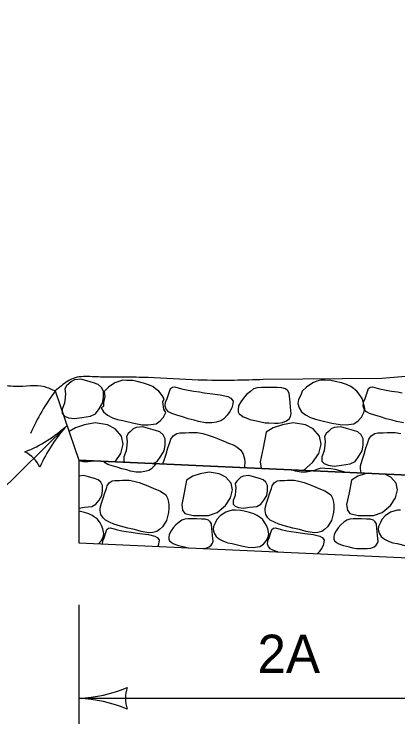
# Model space of a CAD drawing. Extents: x 49991.4 to 50021, y 49987.6 to 50011.4.
# Drawn here: x 50001.389 to 50001.992, y 49990.791 to 49991.906 of the extents above; entities that cross this region are included whole.
import ezdxf

# ---------------------------------------------------------------- set-up
doc = ezdxf.new("R2010")
doc.units = 0
for name, color, linetype in [('Level 1', 7, 'Continuous'), ('Level 2', 7, 'Continuous'), ('Level 3', 7, 'Continuous')]:
    doc.layers.add(name, color=color, linetype=linetype)

msp = doc.modelspace()

# ---------------------------------------------------------------- linework, layer by layer
at = {"layer": 'Level 1'}
for p, q in [((50001.4535, 49991.3139), (50001.4905, 49991.2052)), ((50001.4905, 49991.2052), (50001.4905, 49991.0752))]:
    msp.add_line(p, q, dxfattribs=at)
for points in [[(50006.8341, 49992.9155), (50006.2939, 49992.7804), (50006.1193, 49992.7186), (50006.0287, 49992.663), (50005.1465, 49992.663), (50002.1692, 49991.1744), (50001.4905, 49991.2052)], [(50002.2619, 49991.3557), (50002.1973, 49991.353), (50001.9665, 49991.3333), (50001.7803, 49991.3318)], [(50002.0003, 49991.2638), (50001.9897, 49991.2658), (50001.9826, 49991.268), (50001.9734, 49991.2703), (50001.9643, 49991.2734), (50001.9552, 49991.2757), (50001.9473, 49991.2783), (50001.9422, 49991.2813), (50001.9387, 49991.2855), (50001.937, 49991.29), (50001.9375, 49991.2963), (50001.9402, 49991.3021), (50001.9427, 49991.3099), (50001.9454, 49991.3175), (50001.9483, 49991.32), (50001.952, 49991.3204), (50001.9626, 49991.3173), (50001.9734, 49991.3151), (50001.9818, 49991.3137), (50001.9912, 49991.3124), (50001.9986, 49991.311)], [(50001.5475, 49991.2026), (50001.5565, 49991.2157), (50001.5604, 49991.2304), (50001.5575, 49991.243), (50001.5476, 49991.2546), (50001.5353, 49991.2609), (50001.5161, 49991.2636), (50001.4994, 49991.2609), (50001.4851, 49991.256), (50001.4752, 49991.25)], [(50001.607, 49991.1999), (50001.6137, 49991.2033), (50001.6194, 49991.2112), (50001.6246, 49991.2199), (50001.6263, 49991.2286), (50001.626, 49991.2385), (50001.6228, 49991.2448), (50001.6179, 49991.2495), (50001.6108, 49991.2519), (50001.5999, 49991.2551), (50001.5908, 49991.2575), (50001.5805, 49991.2564), (50001.5758, 49991.2542), (50001.5716, 49991.2501), (50001.5682, 49991.247), (50001.5655, 49991.2423), (50001.5665, 49991.2345), (50001.566, 49991.2289), (50001.565, 49991.2197), (50001.561, 49991.2105), (50001.5613, 49991.2036), (50001.5629, 49991.2019)], [(50001.8438, 49991.1892), (50001.8576, 49991.2013), (50001.8674, 49991.2157), (50001.8714, 49991.2304), (50001.8684, 49991.243), (50001.8586, 49991.2546), (50001.8463, 49991.2609), (50001.8271, 49991.2636), (50001.8103, 49991.2609), (50001.796, 49991.256), (50001.7846, 49991.249), (50001.7798, 49991.2246), (50001.7754, 49991.2027), (50001.7768, 49991.1924), (50001.7769, 49991.1922)], [(50001.6227, 49991.1992), (50001.6243, 49991.2052), (50001.6275, 49991.2148), (50001.6305, 49991.2246), (50001.6334, 49991.2329), (50001.6349, 49991.2383), (50001.6388, 49991.2435), (50001.6442, 49991.2473), (50001.6494, 49991.2479), (50001.6578, 49991.2482), (50001.6637, 49991.2488), (50001.6763, 49991.2486), (50001.6854, 49991.2468), (50001.6952, 49991.2441), (50001.7031, 49991.2414), (50001.7085, 49991.2392), (50001.7174, 49991.2356), (50001.7257, 49991.232), (50001.7344, 49991.2289), (50001.7393, 49991.2255), (50001.7452, 49991.2208), (50001.7486, 49991.2146), (50001.7506, 49991.2072), (50001.7511, 49991.2023), (50001.7509, 49991.1951), (50001.7507, 49991.1934)], [(50001.9338, 49991.1851), (50001.9328, 49991.1913), (50001.9328, 49991.196), (50001.9353, 49991.2052), (50001.9385, 49991.2148), (50001.9414, 49991.2246), (50001.9444, 49991.2329), (50001.9458, 49991.2383), (50001.9498, 49991.2435), (50001.9552, 49991.2473), (50001.9604, 49991.2479), (50001.9687, 49991.2482), (50001.9747, 49991.2488), (50001.9872, 49991.2486), (50001.9963, 49991.2468)], [(50001.4905, 49991.2052), (50002.1692, 49991.1744)], [(50001.4905, 49991.2046), (50001.4975, 49991.2033), (50001.5053, 49991.2031), (50001.5138, 49991.2041)], [(50001.6114, 49991.1997), (50001.6087, 49991.1962), (50001.6046, 49991.1917), (50001.6005, 49991.1891), (50001.5944, 49991.1872), (50001.5886, 49991.1861), (50001.5804, 49991.1863), (50001.5716, 49991.188), (50001.5657, 49991.1898), (50001.5581, 49991.1917), (50001.5505, 49991.1943), (50001.5429, 49991.1962), (50001.5363, 49991.1984), (50001.532, 49991.2008), (50001.5299, 49991.2034)], [(50001.9082, 49991.1862), (50001.903, 49991.1879), (50001.8929, 49991.1904), (50001.8863, 49991.1917), (50001.8767, 49991.192), (50001.8708, 49991.1924), (50001.8641, 49991.1906), (50001.859, 49991.1885)], [(50001.4905, 49991.1298), (50001.4994, 49991.1311), (50001.5109, 49991.1326), (50001.5174, 49991.1359), (50001.5222, 49991.1424), (50001.5265, 49991.1497), (50001.5279, 49991.157), (50001.5277, 49991.1652), (50001.525, 49991.1704), (50001.5209, 49991.1743), (50001.515, 49991.1764), (50001.5059, 49991.179), (50001.4984, 49991.1811), (50001.4905, 49991.1802)], [(50001.8578, 49991.1885), (50001.8535, 49991.1872), (50001.8478, 49991.1861), (50001.8396, 49991.1863), (50001.8307, 49991.188), (50001.8248, 49991.1898), (50001.8238, 49991.1901)], [(50001.919, 49991.174), (50001.9149, 49991.1536), (50001.9112, 49991.1354), (50001.9125, 49991.1268), (50001.9162, 49991.1212), (50001.9293, 49991.1182), (50001.9535, 49991.1182), (50001.9671, 49991.123), (50001.9798, 49991.1342), (50001.988, 49991.1462), (50001.9913, 49991.1585), (50001.9888, 49991.1689), (50001.9806, 49991.1786), (50001.9713, 49991.1834)], [(50001.9448, 49991.1846), (50001.9404, 49991.1839), (50001.9285, 49991.1798), (50001.919, 49991.174)], [(50001.5216, 49991.0738), (50001.5254, 49991.0783), (50001.5287, 49991.0843), (50001.5298, 49991.0895), (50001.5283, 49991.0971), (50001.5263, 49991.1026), (50001.5238, 49991.1067), (50001.5197, 49991.1123), (50001.5152, 49991.1156), (50001.5117, 49991.1184), (50001.5062, 49991.1208), (50001.4994, 49991.1231), (50001.491, 49991.1251), (50001.4905, 49991.1252)], [(50001.9957, 49991.1264), (50001.9908, 49991.1268), (50001.9852, 49991.1253), (50001.9803, 49991.1233)], [(50001.6857, 49991.0663), (50001.69, 49991.0669), (50001.6953, 49991.0692), (50001.6986, 49991.0718), (50001.7004, 49991.0747), (50001.7015, 49991.0781), (50001.7007, 49991.0869), (50001.7, 49991.093), (50001.6996, 49991.0975), (50001.6988, 49991.1052), (50001.697, 49991.1083), (50001.6941, 49991.1111), (50001.6892, 49991.1124), (50001.6832, 49991.1126), (50001.6756, 49991.1128), (50001.668, 49991.1128), (50001.6623, 49991.1128), (50001.6569, 49991.1123)], [(50001.9803, 49991.1233), (50001.9717, 49991.1175), (50001.9663, 49991.1121), (50001.9643, 49991.107), (50001.9614, 49991.1012), (50001.9606, 49991.096), (50001.9622, 49991.0904), (50001.9655, 49991.0854), (50001.9707, 49991.0811), (50001.977, 49991.0777), (50001.9838, 49991.0755), (50001.9906, 49991.074), (50002.0049, 49991.0705)], [(50001.6569, 49991.1123), (50001.6522, 49991.1108), (50001.6479, 49991.1076), (50001.643, 49991.1035), (50001.6389, 49991.0988), (50001.6356, 49991.0942), (50001.6325, 49991.0886), (50001.6319, 49991.0841), (50001.6319, 49991.0809), (50001.6331, 49991.0785), (50001.6358, 49991.0764), (50001.6387, 49991.0744), (50001.6426, 49991.0729), (50001.6471, 49991.071), (50001.6516, 49991.0699), (50001.6561, 49991.0692), (50001.6615, 49991.0677), (50001.663, 49991.0674)], [(50001.5277, 49991.0735), (50001.5281, 49991.0785), (50001.5304, 49991.0833), (50001.5324, 49991.0899), (50001.5347, 49991.0962)], [(50001.5347, 49991.0962), (50001.5371, 49991.0983), (50001.5402, 49991.0986), (50001.549, 49991.096), (50001.5581, 49991.0942), (50001.565, 49991.093), (50001.5728, 49991.0919), (50001.579, 49991.0908), (50001.5864, 49991.09), (50001.5997, 49991.0882), (50001.61, 49991.0859), (50001.6137, 49991.0837), (50001.6165, 49991.08), (50001.6161, 49991.0762), (50001.6151, 49991.0712), (50001.6142, 49991.0696)], [(50001.8033, 49991.061), (50001.802, 49991.0613), (50001.7954, 49991.0636), (50001.7911, 49991.066), (50001.7883, 49991.0695), (50001.7868, 49991.0733), (50001.7872, 49991.0785), (50001.7895, 49991.0833), (50001.7915, 49991.0899), (50001.7938, 49991.0962)], [(50001.7938, 49991.0962), (50001.7963, 49991.0983), (50001.7993, 49991.0986), (50001.8082, 49991.096), (50001.8172, 49991.0942), (50001.8242, 49991.093), (50001.832, 49991.0919), (50001.8381, 49991.0908), (50001.8455, 49991.09), (50001.8588, 49991.0882), (50001.8691, 49991.0859), (50001.8728, 49991.0837), (50001.8757, 49991.08), (50001.8753, 49991.0762), (50001.8742, 49991.0712), (50001.8716, 49991.0662), (50001.8679, 49991.0613), (50001.865, 49991.0582)], [(50001.4905, 49991.0752), (50002.1692, 49991.0444)]]:
    msp.add_lwpolyline(points, dxfattribs=at)
for points in [[(50001.4905, 49991.2052), (50001.4905, 49991.0752), (50002.1692, 49991.0444), (50005.1465, 49992.533), (50006.0287, 49992.533), (50006.0287, 49992.663), (50005.1465, 49992.663), (50002.1692, 49991.1744)], [(50001.4835, 49991.3312), (50001.4788, 49991.3289), (50001.4746, 49991.3249), (50001.4712, 49991.3218), (50001.4685, 49991.3171), (50001.4695, 49991.3092), (50001.469, 49991.3036), (50001.468, 49991.2945), (50001.4641, 49991.2853), (50001.4643, 49991.2783), (50001.468, 49991.2745), (50001.4744, 49991.2718), (50001.4838, 49991.2707), (50001.4951, 49991.2723), (50001.5089, 49991.2741), (50001.5167, 49991.2781), (50001.5224, 49991.2859), (50001.5276, 49991.2947), (50001.5293, 49991.3034), (50001.5291, 49991.3133), (50001.5259, 49991.3195), (50001.5209, 49991.3242), (50001.5138, 49991.3267), (50001.503, 49991.3298), (50001.4939, 49991.3323)], [(50001.5473, 49991.3266), (50001.5369, 49991.3196), (50001.5305, 49991.3131), (50001.5315, 49991.3054), (50001.5293, 49991.2959), (50001.5291, 49991.2895), (50001.5256, 49991.2872), (50001.5295, 49991.2811), (50001.5357, 49991.276), (50001.5433, 49991.2719), (50001.5514, 49991.2692), (50001.5596, 49991.2675), (50001.5768, 49991.2632), (50001.5899, 49991.2607), (50001.5992, 49991.2605), (50001.6118, 49991.2621), (50001.6184, 49991.2668), (50001.6233, 49991.2726), (50001.6273, 49991.2798), (50001.6241, 49991.2852), (50001.6223, 49991.2966), (50001.6243, 49991.3017), (50001.6214, 49991.3066), (50001.6164, 49991.3134), (50001.611, 49991.3174), (50001.6068, 49991.3207), (50001.6002, 49991.3237), (50001.5921, 49991.3263), (50001.582, 49991.3288), (50001.5753, 49991.3302), (50001.5657, 49991.3304), (50001.5598, 49991.3308), (50001.5532, 49991.329)], [(50001.8582, 49991.3268), (50001.8479, 49991.3198), (50001.8415, 49991.3133), (50001.839, 49991.3073), (50001.8356, 49991.3004), (50001.8346, 49991.2941), (50001.8365, 49991.2874), (50001.8405, 49991.2813), (50001.8466, 49991.2762), (50001.8543, 49991.2721), (50001.8624, 49991.2695), (50001.8705, 49991.2677), (50001.8878, 49991.2634), (50001.9008, 49991.261), (50001.9102, 49991.2607), (50001.9227, 49991.2623), (50001.9294, 49991.267), (50001.9343, 49991.2728), (50001.9382, 49991.28), (50001.9395, 49991.2863), (50001.9377, 49991.2954), (50001.9353, 49991.3019), (50001.9323, 49991.3069), (50001.9274, 49991.3136), (50001.922, 49991.3176), (50001.9178, 49991.321), (50001.9111, 49991.3239), (50001.903, 49991.3266), (50001.8929, 49991.329), (50001.8863, 49991.3304), (50001.8767, 49991.3306), (50001.8708, 49991.331), (50001.8641, 49991.3292)], [(50001.6344, 49991.3175), (50001.6374, 49991.32), (50001.6411, 49991.3204), (50001.6517, 49991.3173), (50001.6625, 49991.3151), (50001.6709, 49991.3137), (50001.6802, 49991.3124), (50001.6876, 49991.311), (50001.6965, 49991.3101), (50001.7125, 49991.3079), (50001.7248, 49991.3052), (50001.7292, 49991.3025), (50001.7327, 49991.2981), (50001.7322, 49991.2936), (50001.7309, 49991.2875), (50001.7277, 49991.2815), (50001.7233, 49991.2757), (50001.7184, 49991.2703), (50001.7135, 49991.2672), (50001.7061, 49991.2649), (50001.6992, 49991.2636), (50001.6893, 49991.2638), (50001.6787, 49991.2658), (50001.6716, 49991.268), (50001.6625, 49991.2703), (50001.6534, 49991.2734), (50001.6443, 49991.2757), (50001.6364, 49991.2783), (50001.6312, 49991.2813), (50001.6278, 49991.2855), (50001.626, 49991.29), (50001.6265, 49991.2963), (50001.6292, 49991.3021), (50001.6317, 49991.3099)], [(50001.7708, 49991.3187), (50001.7651, 49991.317), (50001.7599, 49991.3131), (50001.754, 49991.3082), (50001.7491, 49991.3026), (50001.7452, 49991.297), (50001.7415, 49991.2903), (50001.7407, 49991.2849), (50001.7407, 49991.2811), (50001.7422, 49991.2782), (50001.7454, 49991.2758), (50001.7488, 49991.2733), (50001.7535, 49991.2715), (50001.7589, 49991.2693), (50001.7644, 49991.2679), (50001.7698, 49991.267), (50001.7762, 49991.2652), (50001.7833, 49991.2639), (50001.7892, 49991.2639), (50001.7976, 49991.2634), (50001.8038, 49991.2634), (50001.8104, 49991.2643), (50001.8168, 49991.267), (50001.8207, 49991.2702), (50001.823, 49991.2737), (50001.8242, 49991.2778), (50001.8232, 49991.2883), (50001.8225, 49991.2957), (50001.822, 49991.3011), (50001.821, 49991.3102), (50001.8188, 49991.314), (50001.8153, 49991.3174), (50001.8094, 49991.319), (50001.8023, 49991.3192), (50001.7932, 49991.3194), (50001.7841, 49991.3194), (50001.7772, 49991.3194)], [(50001.8914, 49991.2564), (50001.8868, 49991.2542), (50001.8826, 49991.2501), (50001.8791, 49991.247), (50001.8764, 49991.2423), (50001.8774, 49991.2345), (50001.8769, 49991.2289), (50001.8759, 49991.2197), (50001.872, 49991.2105), (50001.8722, 49991.2036), (50001.8759, 49991.1998), (50001.8823, 49991.1971), (50001.8917, 49991.1959), (50001.903, 49991.1975), (50001.9168, 49991.1993), (50001.9247, 49991.2033), (50001.9303, 49991.2112), (50001.9355, 49991.2199), (50001.9372, 49991.2286), (50001.937, 49991.2385), (50001.9338, 49991.2448), (50001.9289, 49991.2495), (50001.9217, 49991.2519), (50001.9109, 49991.2551), (50001.9018, 49991.2575)], [(50001.6598, 49991.174), (50001.6558, 49991.1536), (50001.6521, 49991.1354), (50001.6534, 49991.1268), (50001.657, 49991.1212), (50001.6702, 49991.1182), (50001.6944, 49991.1182), (50001.7079, 49991.123), (50001.7207, 49991.1342), (50001.7289, 49991.1462), (50001.7321, 49991.1585), (50001.7297, 49991.1689), (50001.7215, 49991.1786), (50001.7112, 49991.1839), (50001.6952, 49991.1861), (50001.6813, 49991.1839), (50001.6694, 49991.1798)], [(50001.7489, 49991.1801), (50001.745, 49991.1783), (50001.7415, 49991.1749), (50001.7386, 49991.1723), (50001.7363, 49991.1684), (50001.7372, 49991.1618), (50001.7368, 49991.1572), (50001.7359, 49991.1495), (50001.7327, 49991.1419), (50001.7329, 49991.1361), (50001.7359, 49991.1329), (50001.7413, 49991.1307), (50001.7491, 49991.1298), (50001.7585, 49991.1311), (50001.77, 49991.1326), (50001.7766, 49991.1359), (50001.7813, 49991.1424), (50001.7856, 49991.1497), (50001.787, 49991.157), (50001.7868, 49991.1652), (50001.7842, 49991.1704), (50001.7801, 49991.1743), (50001.7741, 49991.1764), (50001.7651, 49991.179), (50001.7575, 49991.1811)], [(50001.5472, 49991.1731), (50001.5542, 49991.1733), (50001.5591, 49991.1738), (50001.5695, 49991.1736), (50001.5771, 49991.1721), (50001.5853, 49991.1699), (50001.5919, 49991.1677), (50001.5964, 49991.1658), (50001.6038, 49991.1628), (50001.6108, 49991.1598), (50001.618, 49991.1572), (50001.6221, 49991.1544), (50001.627, 49991.1505), (50001.6299, 49991.1453), (50001.6315, 49991.1391), (50001.6319, 49991.135), (50001.6317, 49991.129), (50001.6313, 49991.1231), (50001.6297, 49991.1165), (50001.6282, 49991.1102), (50001.6258, 49991.1061), (50001.6219, 49991.1005), (50001.6171, 49991.0962), (50001.6128, 49991.0932), (50001.6067, 49991.0914), (50001.6007, 49991.0908), (50001.5886, 49991.0932), (50001.5782, 49991.096), (50001.5677, 49991.0981), (50001.5562, 49991.1016), (50001.5457, 49991.1048), (50001.5388, 49991.1076), (50001.5322, 49991.1111), (50001.5285, 49991.1147), (50001.5252, 49991.1197), (50001.5242, 49991.1259), (50001.5242, 49991.1298), (50001.5262, 49991.1374), (50001.5289, 49991.1455), (50001.5314, 49991.1537), (50001.5338, 49991.1606), (50001.5351, 49991.1651), (50001.5384, 49991.1693), (50001.5429, 49991.1725)], [(50001.8063, 49991.1731), (50001.8133, 49991.1733), (50001.8182, 49991.1738), (50001.8287, 49991.1736), (50001.8363, 49991.1721), (50001.8445, 49991.1699), (50001.851, 49991.1677), (50001.8555, 49991.1658), (50001.8629, 49991.1628), (50001.8699, 49991.1598), (50001.8771, 49991.1572), (50001.8812, 49991.1544), (50001.8861, 49991.1505), (50001.889, 49991.1453), (50001.8906, 49991.1391), (50001.891, 49991.135), (50001.8908, 49991.129), (50001.8904, 49991.1231), (50001.8888, 49991.1165), (50001.8873, 49991.1102), (50001.8849, 49991.1061), (50001.881, 49991.1005), (50001.8763, 49991.0962), (50001.872, 49991.0932), (50001.8658, 49991.0914), (50001.8599, 49991.0908), (50001.8477, 49991.0932), (50001.8373, 49991.096), (50001.8268, 49991.0981), (50001.8153, 49991.1016), (50001.8049, 49991.1048), (50001.7979, 49991.1076), (50001.7913, 49991.1111), (50001.7876, 49991.1147), (50001.7843, 49991.1197), (50001.7833, 49991.1259), (50001.7833, 49991.1298), (50001.7854, 49991.1374), (50001.788, 49991.1455), (50001.7905, 49991.1537), (50001.793, 49991.1606), (50001.7942, 49991.1651), (50001.7975, 49991.1693), (50001.802, 49991.1725)], [(50001.7212, 49991.1233), (50001.7126, 49991.1175), (50001.7072, 49991.1121), (50001.7052, 49991.107), (50001.7023, 49991.1012), (50001.7015, 49991.096), (50001.7031, 49991.0904), (50001.7064, 49991.0854), (50001.7115, 49991.0811), (50001.7179, 49991.0777), (50001.7247, 49991.0755), (50001.7314, 49991.074), (50001.7458, 49991.0705), (50001.7567, 49991.0684), (50001.7645, 49991.0682), (50001.7749, 49991.0695), (50001.7805, 49991.0734), (50001.7846, 49991.0783), (50001.7879, 49991.0843), (50001.7889, 49991.0895), (50001.7874, 49991.0971), (50001.7854, 49991.1026), (50001.7829, 49991.1067), (50001.7788, 49991.1123), (50001.7743, 49991.1156), (50001.7708, 49991.1184), (50001.7653, 49991.1208), (50001.7585, 49991.1231), (50001.7501, 49991.1251), (50001.7446, 49991.1262), (50001.7366, 49991.1264), (50001.7316, 49991.1268), (50001.7261, 49991.1253)], [(50001.9161, 49991.1123), (50001.9114, 49991.1108), (50001.907, 49991.1076), (50001.9021, 49991.1035), (50001.898, 49991.0988), (50001.8947, 49991.0942), (50001.8917, 49991.0886), (50001.891, 49991.0841), (50001.891, 49991.0809), (50001.8923, 49991.0785), (50001.8949, 49991.0764), (50001.8978, 49991.0744), (50001.9017, 49991.0729), (50001.9062, 49991.071), (50001.9107, 49991.0699), (50001.9153, 49991.0692), (50001.9206, 49991.0677), (50001.9265, 49991.0665), (50001.9315, 49991.0665), (50001.9384, 49991.0662), (50001.9436, 49991.0662), (50001.9491, 49991.0669), (50001.9544, 49991.0692), (50001.9577, 49991.0718), (50001.9596, 49991.0747), (50001.9606, 49991.0781), (50001.9598, 49991.0869), (50001.9592, 49991.093), (50001.9588, 49991.0975), (50001.9579, 49991.1052), (50001.9561, 49991.1083), (50001.9532, 49991.1111), (50001.9483, 49991.1124), (50001.9423, 49991.1126), (50001.9347, 49991.1128), (50001.9272, 49991.1128), (50001.9214, 49991.1128)]]:
    msp.add_lwpolyline(points, close=True, dxfattribs=at)
msp.add_arc((50001.7595, 49991.0901), 0.3791, 143.8272, 155.5248, dxfattribs=at)
for points in [[(50000.9415, 49991.3419), (50000.9706, 49991.3427), (50001.1375, 49991.3367), (50001.3349, 49991.3192), (50001.3764, 49991.3222), (50001.3913, 49991.3214), (50001.4365, 49991.3207), (50001.4535, 49991.3139)], [(50001.7803, 49991.3318), (50001.7346, 49991.3305), (50001.6782, 49991.331), (50001.5992, 49991.3348), (50001.5805, 49991.3354), (50001.5619, 49991.3356), (50001.5246, 49991.3358), (50001.5113, 49991.3363), (50001.4976, 49991.3365), (50001.4847, 49991.3346), (50001.4733, 49991.3292), (50001.4535, 49991.3139)]]:
    msp.add_spline(points, degree=3, dxfattribs=at)
at = {"layer": 'Level 3'}
for p, q in [((50001.472, 49991.2595), (50001.2234, 49991.0151)), ((50001.4905, 49990.9781), (50001.4905, 49990.791)), ((50002.1692, 49990.831), (50001.4905, 49990.831))]:
    msp.add_line(p, q, dxfattribs=at)
for centre, radius, start, end in [((50001.3228, 49991.4244), 0.2223, 291.9687, 312.1522), ((50001.6433, 49991.1017), 0.233, 137.34, 156.5898), ((50001.3805, 49991.1697), 0.0548, 26.6515, 62.3738), ((50001.479, 49991.0637), 0.233, 272.8273, 292.0772), ((50001.6187, 49990.831), 0.0548, 162.1388, 197.8612), ((50001.4813, 49990.6089), 0.2223, 67.456, 87.6395)]:
    msp.add_arc(centre, radius, start, end, dxfattribs=at)

# ---------------------------------------------------------------- texts
at = {"layer": 'Level 2'}
msp.add_text('2A', height=0.06, dxfattribs=at).set_placement((50001.7712, 49990.871))

doc.saveas('drawing.dxf')
